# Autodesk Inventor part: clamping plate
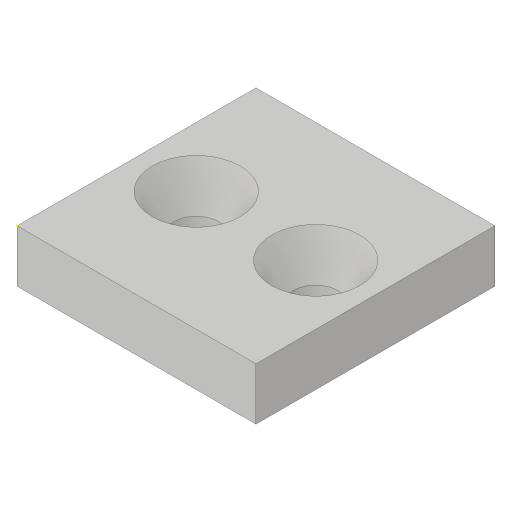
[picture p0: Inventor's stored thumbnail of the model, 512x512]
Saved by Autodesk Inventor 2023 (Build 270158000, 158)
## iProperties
Created: 2016-03
Part Number: clamping plate
Material: Generic
Document SubType Name: Modeling
Designer: Sandeep
Density: 1 g/cm^3
Appearance: Default
Mass: 6.41192 g
Surface Area: 30.6752 cm^2
Volume: 6.41192 cm^3
Author: Sandeep
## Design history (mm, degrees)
sketch "Sketch1"
  geometry: L1 (0, 0)-(32, 0); L2 (32, 0)-(32, 32); L3 (32, 32)-(0, 32); L4 (0, 32)-(0, 0)
  constraints: 8 end point, 2 parallel, 1 horizontal, 1 perpendicular
  dimensions: "d0" = 32 distance between parallel lines of L1 L3; "d1" = 32 distance of L2.end L3.end
extrude "Extrusion1" new body sketch "Sketch1" distance "d2" = 7; taper "d3" = 0 deg
sketch "Sketch2"
  geometry: 1 further point
sketch "Sketch3"
  geometry: 1 further point
hole "Hole2" diameter "d15" = 6; stored, may be unused: countersink angle "d19" = 60 deg, drill point angle "d21" = 118 deg; dims "d13" = 8, "d14" = 16, "d16" = 6, "d17" = 11.78, "d18" = 2, "d20" = 8
sketch "Sketch4"
  geometry: 1 further point
hole "Hole3" diameter "d24" = 6; stored, may be unused: countersink angle "d28" = 60 deg, drill point angle "d30" = 118 deg; dims "d22" = 8, "d23" = 16, "d25" = 6, "d26" = 11.78, "d27" = 2, "d29" = 8
body "Solid1"
